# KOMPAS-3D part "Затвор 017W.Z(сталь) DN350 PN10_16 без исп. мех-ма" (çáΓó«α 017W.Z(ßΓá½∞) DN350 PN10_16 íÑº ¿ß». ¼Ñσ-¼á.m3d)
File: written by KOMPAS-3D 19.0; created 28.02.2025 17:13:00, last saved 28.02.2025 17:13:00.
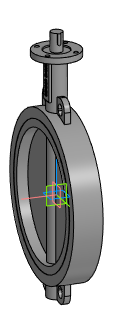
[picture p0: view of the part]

Document properties: Автор: Евгений; Полное имя файла: E:\Dendor Работа Сачек\3D для проекитирвщиков\1.5 Тип 017W.Z Сталь Затвор дисковый поворотный Межфланцевый\stp_Тип 017W.Z(сталь). Затвор без исполн. механизма\Затвор 017W.Z(сталь) DN350 PN10_16 без исп. мех-ма.m3d

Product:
- Part/product: Затвор 017W.Z(сталь) DN350 PN10_16 без исп. мех-ма

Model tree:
1. Операция без истории:1  (labels: Затвор 017W.Z(сталь) DN350 PN10_16 без исп. мех-ма)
